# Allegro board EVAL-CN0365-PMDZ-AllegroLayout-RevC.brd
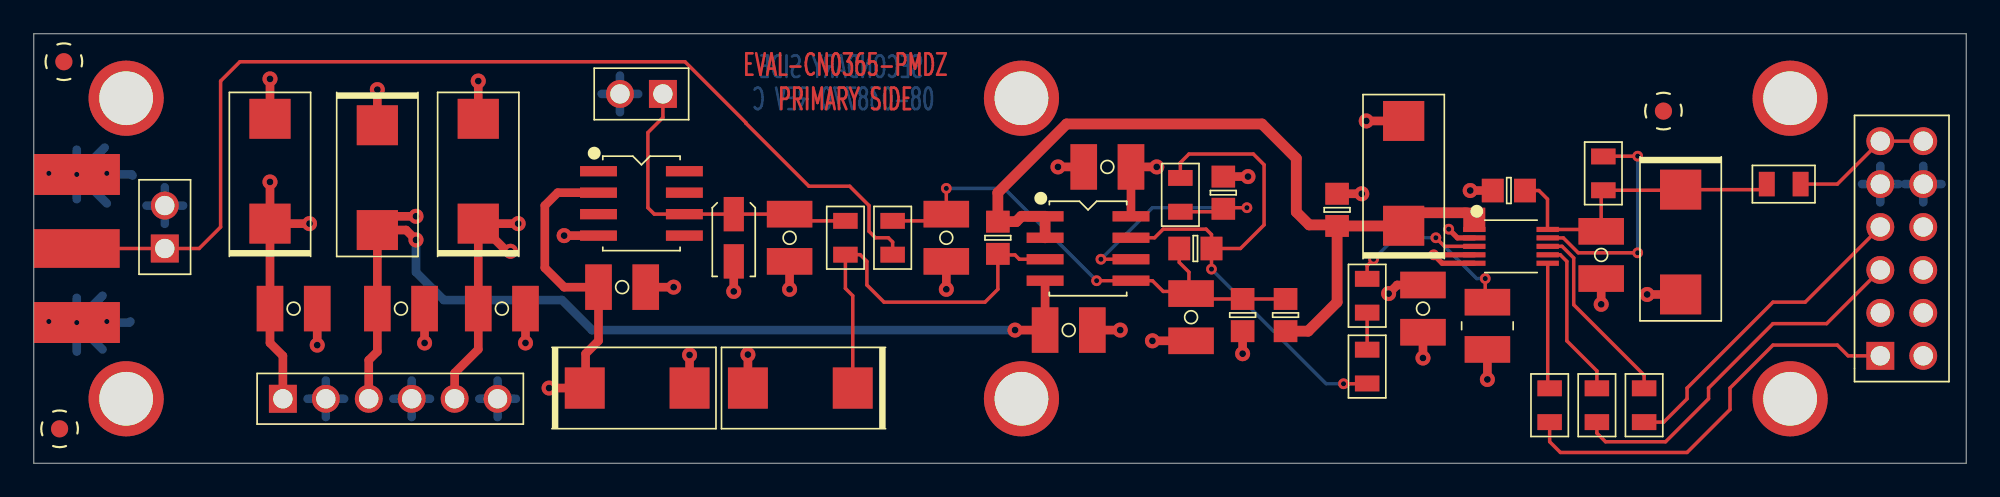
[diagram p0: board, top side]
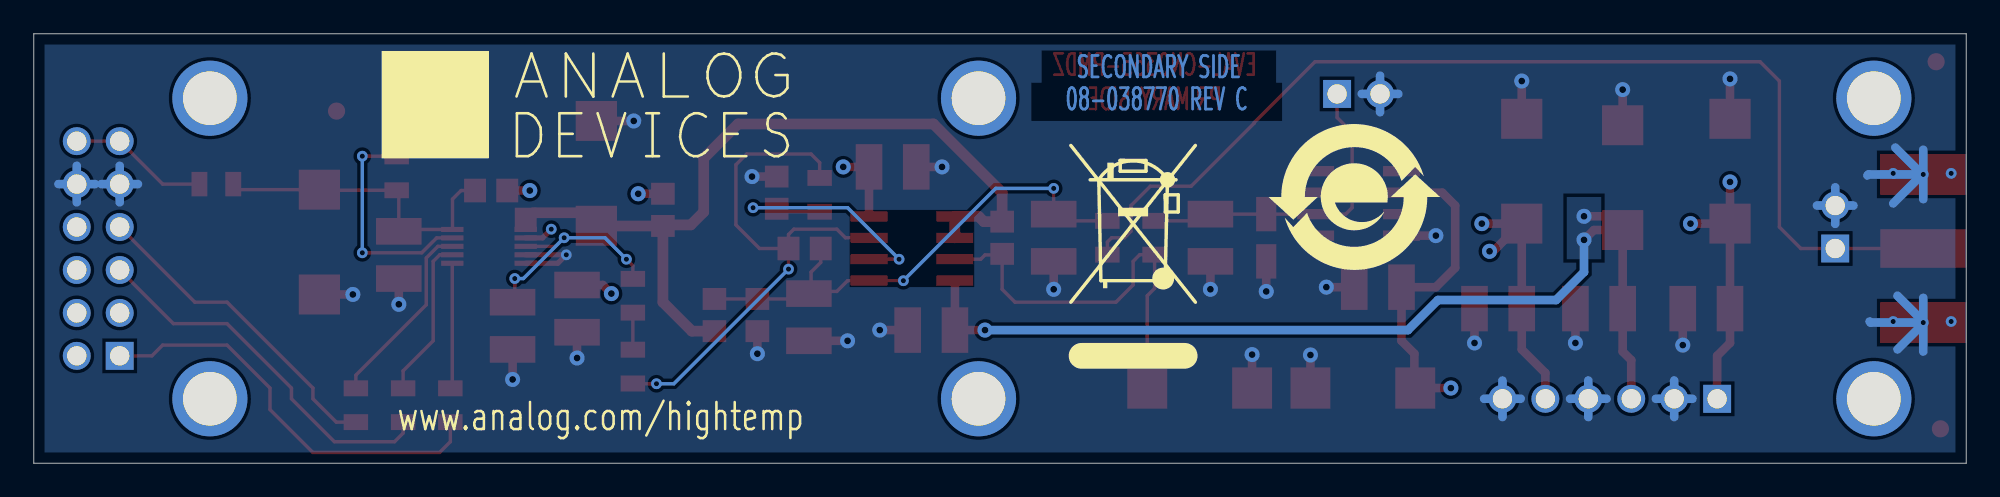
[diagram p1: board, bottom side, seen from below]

Outline 114.3 x 25.4 mm; copper layers: TOP, L2_GND, L3_PWR, BOTTOM. Coordinates in mm from the lower left corner of the outline.
Outline path: 0,25.4 0,0 114.3,0 114.3,25.4 0,25.4

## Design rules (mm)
net group CLS_POWER: nets VS+

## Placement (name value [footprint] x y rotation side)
C1  10uF  [C7343-31]  35.69 4.45 0 top
C2  0.1uF  [C1210]  34.8 10.41 0 top
C3  1uF  [C3216]  41.4 13.34 270 top
C4  0.1uF  [C1210]  44.7 13.34 270 top
C5  0.1uF  [C1210]  61.21 7.87 0 top
C6  TBD1210  [C1210]  53.98 13.34 270 top
C7  2700pF  [C1210-2]  85.98 8.13 270 top
C8  47uF  [C7343-31]  45.34 4.45 180 top
C9  TBD1210  [C1210]  68.45 8.64 270 top
C10  10uF  [C7343-31]  97.41 13.08 270 top
C11  0.1uF  [C1210]  92.71 12.32 270 top
C12  47uF  [C7343-31]  81.03 17.14 90 top
C15  0.1uF  [C1210]  82.17 9.14 270 top
C16  10uF  [C7343-31]  26.29 17.27 90 top
C17  0.1uF  [C1210]  27.69 9.14 0 top
C18  10uF  [C7343-31]  13.97 17.27 90 top
C19  0.1uF  [C1210]  15.37 9.14 0 top
C20  10uF  [C7343-31]  20.32 16.89 270 top
C21  0.1uF  [C1210]  21.72 9.14 0 top
C23  0.1uF  [C1210]  63.5 17.53 180 top
J1  JOHNSON142-0701-801  [CNJOHNSON142-0701-801]  2.54 12.7 180 top
J2  HTSW-106-08-G-D  [CNHDR2X6H330LD35_A]  109.22 6.35 90 top
JP1  0  [R0805H20]  50.8 13.34 90 top
JP2  0  [R0805H20]  67.82 15.88 90 top
JP3  0  [R0805H20]  78.87 5.71 90 top
JP4  0  [R0805H20]  92.84 17.14 90 top
JP5  0  [R0805H20]  89.66 3.43 270 top
JP6  0  [R0805H20]  92.46 3.43 270 top
JP7  0  [R0805H20]  95.25 3.43 270 top
JP8  0  [R0805H20]  103.5 16.51 0 top
NOREF  -  []  93.73 18.03 0 top
NOREF#2  -  []  167 303.53 0 top
NOREF#3  -  []  114.3 2.54 90 top
NOREF#4  -  []  3.81 2.54 0 top
NOREF#5  -  []  60.96 38.1 0 top
NOREF#6  -  []  114.3 27.94 180 top
NOREF#7  -  [unnamed#2]  58.42 21.59 0 top
NOREF#8  -  []  0 0 90 top
NOREF#9  -  [unnamed#2]  103.89 3.81 0 top
NOREF#10  -  []  -233.68 -149.86 0 top
NOREF#11  -  []  396.24 -2.54 0 top
NOREF#12  -  []  0 25.4 0 top
NOREF#13  -  [unnamed#2]  58.42 3.81 0 top
NOREF#14  -  []  0 0 90 top
NOREF#15  -  []  0 0 0 top
NOREF#16  -  [unnamed#2]  96.39 20.83 0 top
NOREF#17  -  []  3.81 27.94 270 top
NOREF#18  -  [unnamed#2]  1.52 2.03 0 top
NOREF#19  -  [unnamed#2]  1.78 23.75 0 top
NOREF#20  -  [unnamed#2]  5.46 3.81 0 top
NOREF#21  -  []  -76.2 -93.98 0 top
NOREF#22  -  []  -91.44 276.86 0 top
NOREF#23  -  [unnamed#2]  5.46 21.59 0 top
NOREF#24  -  [unnamed#2]  103.89 21.59 0 top
NOREF#25  -  []  40.01 22.48 180 bottom
NOREF#26  -  []  36.2 15.75 180 bottom
P1  TSW-101-14-T-D  [CNHDR2X1H428]  7.75 12.7 0 top
P2  TSW-101-14-T-D  [CNHDR2X1H428]  37.21 21.84 90 top
P3  HTSW-106-07-G-S  [CNHDR1X6H343]  14.73 3.81 0 top
R1  49.9  [R0805H20]  48.01 13.34 270 top
R2  TBD0805  [R0805]  57.02 13.34 90 top
R3  TBD0805  [R0805]  70.36 16 270 top
R4  TBD0805  [R0805]  71.5 8.76 270 top
R5  TBD0805  [R0805]  68.71 12.7 0 top
R6  49.9  [R0805H20]  78.87 9.91 90 top
R7  TBD0805  [R0805]  77.09 14.99 90 top
R8  TBD0805  [R0805]  74.04 8.76 90 top
R14  TBD0805  [R0805]  87.25 16.13 0 top
U1  ADR225HRZN  [SO8]  35.94 15.37 270 top
U2  AD8634HRZN  [SO8]  62.36 12.7 270 top
U3  AD7981  [RM10]  87.38 12.83 270 top

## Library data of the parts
C1 C10 C16 C18 C20 = CAPP: Tolerance: 10; User Part Number: UPN; part number: CAPP_SM-10UF,50V,10,E014348,C7343-31; tolerance: 10
C2 C4 C5 C11 C15 C17 C19 C21 C23 = CAP: Tolerance: 5; User Part Number: UPN; alternate symbols: (C0402H22_ALT,C0201-2,C0402_A,C0402_ALT,C0402L_ALT,C0603L_ALT); part number: CAP_SM-0.1UF,25V,5,E018667,C1210; tolerance: 5
C3 = CAPP: Tolerance: 10; User Part Number: UPN; part number: CAPP_SM-1UF,35V,10,E014170,C3216; tolerance: 10
C6 C9 = CAP: User Part Number: UPN; alternate symbols: (C0402H22_ALT,C0201-2,C0402_A,C0402_ALT,C0402L_ALT,C0603L_ALT); part number: CAP_SM-TBD1210,TBD1210,TBD1210,E016202,C1210
C7 = CAP: Tolerance: 5; User Part Number: UPN; alternate symbols: (C0402H22_ALT,C0201-2,C0402_A,C0402_ALT,C0402L_ALT,C0603L_ALT); part number: CAP_SM-2700PF,1000V,5,E021586,C1210-2; tolerance: 5
C8 C12 = CAPP: Tolerance: 10; User Part Number: UPN; part number: CAPP_SM-47UF,16V,10,E021837,C7343-31; tolerance: 10
J1 = CNBNC5P: User Part Number: UPN; alternate symbols: (CNAMPHENOL132255-11_ALT); part number: CNBNC5P_SM-JOHNSON142-0701-801,E000914,CNJOHNSON142-0701-801
J2 = CN12P_V3: User Part Number: UPN; part number: CN12P_V3_TH-HTSW-106-08-G-D,E021590,CNHDR2X6H330LD35_A
JP1-JP8 = RESJMPROPEN: Tolerance: 5; User Part Number: UPN; alternate symbols: (R0402_ALT); part number: RESJMPROPEN_SM-0,E021851,1/8W,5,R0805H20; tolerance: 5
P1 P2 = CN2P: User Part Number: UPN; part number: CN2P_TH-TSW-101-14-T-D,E016220,CNHDR2X1H428
P3 = CN6P: User Part Number: UPN; part number: CN6P_TH-HTSW-106-07-G-S,E021853,CNHDR1X6H343
R1 R6 = RES: Tolerance: 0.1; User Part Number: UPN; alternate symbols: (RRAD984L1500W75H520LD32;TO220H590_ALT;R0402_A;R0603_A,R0402_ALT); part number: RES_SM-49.9,E021588,1/5W,0.1,R0805H20; tolerance: 0.1
R2-R5 R7 R8 R14 = RES: User Part Number: UPN; alternate symbols: (RRAD984L1500W75H520LD32;TO220H590_ALT;R0402_A;R0603_A,R0402_ALT); part number: RES_SM-TBD0805,E004051,TBD0805,TBD0805,R0805
U1 = ADR225: User Part Number: UPN; part number: ADR225_SM-ADR225HRZN,E019946,SO8
U2 = AD8634: User Part Number: UPN; part number: AD8634_SM-AD8634HRZN,E020461,SO8
U3 = AD7981: User Part Number: UPN; part number: AD7981_SM-AD7981,E021331,RM10

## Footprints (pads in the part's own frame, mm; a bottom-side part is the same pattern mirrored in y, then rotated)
C1210
  rect 1.575x2.692 smd: 1(-1.397,0) 2(1.397,0)
C1210-2
  rect 1.575x2.692 smd: 1(-1.397,0) 2(1.397,0)
C3216
  rect 2.032x1.194 smd: N(1.397,0) P(-1.397,0)
C7343-31
  rect 2.362x2.438 smd: N(3.1,0) P(-3.1,0)
CNHDR1X6H343
  rect 1.651x1.651 hole 1.143: 1(0,0)
  round 1.651 hole 1.143: 2(2.54,0) 3(5.08,0) 4(7.62,0) 5(10.16,0) 6(12.7,0)
CNHDR2X1H428
  rect 1.651x1.651 hole 1.143: 1(0,0)
  round 1.651 hole 1.143: 2(0,2.54)
CNHDR2X6H330LD35_A
  rect 1.651x1.651 hole 1.143: 1(0,0)
  round 1.651 hole 1.143: 2(2.54,0) 3(5.08,0) 4(7.62,0) 5(10.16,0) 6(12.7,0) 7(0,-2.54) 8(2.54,-2.54) 9(5.08,-2.54) 10(7.62,-2.54) 11(10.16,-2.54) 12(12.7,-2.54)
CNJOHNSON142-0701-801
  rect 5.08x2.286 smd: 1(0,0)
  rect 5.08x2.413 smd: 2(0,4.381) 3(0,4.381) 4(0,-4.381) 5(0,-4.381)
R0805
  rect 1.295x1.397 smd: 1(-0.953,0) 2(0.953,0)
R0805H20
  rect 0.94x1.448 smd: 1(-1,0) 2(1,0)
RM10
  rect 0.305x1.321 smd: 1(-1,-2.171) 2(-0.5,-2.171) 3(0,-2.171) 4(0.5,-2.171) 5(1,-2.171) 6(1,2.171) 7(0.5,2.171) 8(0,2.171) 9(-0.5,2.171) 10(-1,2.171)
SO8
  rect 0.61x2.184 smd: 1(-1.905,-2.54) 2(-0.635,-2.54) 3(0.635,-2.54) 4(1.905,-2.54) 5(1.905,2.54) 6(0.635,2.54) 7(-0.635,2.54) 8(-1.905,2.54)
unnamed#2
  round 4.445 hole 3.175 unplated: (0,0)

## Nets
AGND: C1.N(N2) C2.2(N2) C3.N(N2) C4.2(N2) C5.2(N2) C6.2(N2) C7.2(N2) C8.N(N2) C9.2(N2) C10.N(N2) C11.2(N2) C12.N(N2) C15.2(N2) C16.N(N2) C17.2(N2) C18.N(N2) C19.2(N2) C20.P(N1) C21.2(N2) C23.2(N2) J1.2(SH1) J1.3(SH2) J1.4(SH3) J1.5(SH4) J2.5(GND1) J2.11(GND2) P1.2(N2) P2.2(N2) P3.2(N2) P3.4(N4) P3.6(N6) R3.1(N1) R4.2(N2) U1.4(GND) U3.4(IN-) U3.5(GND)
VDD: C15.1(N1) C16.P(N1) C17.1(N1) P3.5(N5) R7.2(N2) R14.1(N1) U3.2(VDD)
CNV: JP5.1(S1) U3.6(CNV)
REF: C3.P(N1) C4.1(N1) P2.1(N1) R1.1(N1) U1.6(OUTPUT)
REF_BUF: C12.P(N1) R2.2(N2) R7.1(N1) R8.1(N1) U2.1(OUT) U2.2(-IN) U3.1(REF)
SCK: JP7.1(S1) U3.8(SCK)
SDI: JP4.2(S2) U3.9(SDI)
SDO: JP6.1(S1) U3.7(SDO)
UNNAMED_2_AD7981_I1_IN: C7.1(N1) R6.2(N2) U3.3(IN+)
UNNAMED_2_AD8634_I44__1: JP2.1(S1) R3.2(N2) U2.6(-IN)
UNNAMED_2_AD8634_I44_OUT: JP2.2(S2) JP3.1(S1) R5.2(N2) U2.7(OUT)
UNNAMED_2_AD8634_I149_: C8.P(N1) R1.2(N2) R2.1(N1) U2.3(+IN)
UNNAMED_2_CAP_I204_N1: C6.1(N1) C9.1(N1) JP1.2(S2) R4.1(N1) R5.1(N1) R8.2(N2) U2.5(+IN)
UNNAMED_2_CN12PV3_I180_P1: J2.1(P1) JP5.2(S2)
UNNAMED_2_CN12PV3_I180_P3: J2.3(P3) JP6.2(S2)
UNNAMED_2_CN12PV3_I180_P4: J2.4(P4) JP7.2(S2)
UNNAMED_2_CN12PV3_I180_VCC1: J2.6(VCC1) J2.12(VCC2) JP8.2(S2)
UNNAMED_2_CNBNC5P_I137_CNTR: J1.1(CNTR) JP1.1(S1) P1.1(N1)
UNNAMED_2_RES_I189_N1: JP3.2(S2) R6.1(N1)
VIO: C10.P(N1) C11.1(N1) JP4.1(S1) JP8.1(S1) R14.2(N2) U3.10(VIO)
VS+: C1.P(N1) C2.1(N1) C18.P(N1) C19.1(N1) C23.1(N1) P3.1(N1) U1.2(VS) U2.8(V+)
VS-: C5.1(N1) C20.N(N2) C21.1(N1) P3.3(N3) U2.4(V-)

Pads without a net: J2 2 7 8 9 10; U1 1 3 5 7 8

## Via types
v1: diameter 0.635, hole 0.305, TOP to BOTTOM, 19 vias
v2: diameter 0.889, hole 0.406, TOP to BOTTOM, 35 vias

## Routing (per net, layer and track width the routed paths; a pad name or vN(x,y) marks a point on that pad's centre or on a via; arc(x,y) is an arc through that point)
AGND: length 130.2
  TOP w0.305: U3.4 v1(82.8,12.33) 83.3,11.83 U3.5
  TOP w0.508: C18.N v2(13.97,22.73) ; C1.N v2(38.79,6.4) ; R4.2 v2(71.5,6.48) ; C7.2 v2(85.98,4.95) ; C16.N v2(26.29,22.61) ; U1.4 v2(31.37,13.46) ; C17.2 v2(29.08,7.11) ; C10.N v2(95.43,9.98) ; C4.2 v2(44.7,10.29) ; C6.2 v2(53.98,10.29) ; R3.1 v2(71.82,16.95) ; C21.2 v2(23.11,7.11) ; C5.2 v2(64.26,7.87) ; C19.2 v2(16.76,6.99) ; C9.2 v2(66.17,7.24) ; C3.N v2(41.4,10.16) ; C11.2 v2(92.71,9.4) ; C23.2 v2(60.58,17.53) ; C15.2 v2(82.17,6.22) ; C12.N v2(78.81,20.25) ; C20.P v2(20.32,22.1) ; 42.24,4.45 v2(42.24,6.42) ; C2.2 v2(37.85,10.41)
  L2_GND w0.508: J2.11 111.76,17.59 ; J2.11 111.76,15.43 ; J2.11 112.84,16.51 ; J2.11 110.68,16.51 ; 21.27,3.81 P3.4 ; P3.4 22.35,2.73 ; P3.4 23.43,3.81 ; P3.4 22.35,4.89 ; 34.67,21.84 35.75,21.84 ; 34.67,21.84 33.59,21.84 ; 34.67,21.84 34.67,22.92 ; 34.67,21.84 34.67,20.76 ; 27.43,2.73 P3.6 ; P3.6 27.43,4.89 ; P3.6 28.51,3.81 ; P3.6 26.35,3.81 ; 108.14,16.51 J2.5 ; J2.5 109.22,15.43 ; J2.5 109.22,17.59 ; J2.5 110.3,16.51 ; P3.2 17.27,4.89 ; P3.2 18.35,3.81 ; P3.2 16.19,3.81 ; P3.2 17.27,2.73 ; P1.2 8.83,15.24 ; P1.2 6.67,15.24 ; P1.2 7.75,14.16 ; P1.2 7.75,16.32
  BOTTOM w0.508: P3.6 27.43,4.89 ; P3.6 26.35,3.81 ; P3.6 28.51,3.81 ; P3.6 27.43,2.73 ; 4.06,9.91 2.54,8.38 ; 2.54,8.38 2.54,9.78 ; 2.54,8.38 v1(2.54,8.32) ; P3.2 17.27,4.89 ; P3.2 17.27,2.73 ; P3.2 18.35,3.81 ; P3.2 16.19,3.81 ; J2.5 109.22,17.59 ; J2.5 110.3,16.51 ; J2.5 108.14,16.51 ; J2.5 109.22,15.43 ; 4.25,8.32 5.65,8.32 5.71,8.38 ; 4.25,8.32 v1(4.32,8.38) ; 4.25,8.32 v1(2.54,8.32) ; 4.25,17.08 2.6,17.08 ; 4.25,17.08 v1(4.32,17.14) ; 4.25,17.08 5.78,17.08 5.84,17.02 ; 2.6,17.08 v1(2.54,17.08) ; 2.6,17.08 4.19,18.67 ; 2.6,17.08 4.32,15.37 ; J2.11 112.84,16.51 ; J2.11 110.68,16.51 ; J2.11 111.76,15.43 ; J2.11 111.76,17.59 ; 4.06,6.73 2.54,8.25 ; 2.54,8.25 v1(2.54,8.32) ; 2.54,8.25 2.54,6.6 ; 34.67,21.84 35.75,21.84 ; 34.67,21.84 34.67,22.92 ; 34.67,21.84 33.59,21.84 ; 34.67,21.84 34.67,20.76 ; v1(2.54,17.08) 2.54,15.62 ; v1(2.54,17.08) 2.54,18.54 ; P1.2 8.83,15.24 ; P1.2 6.67,15.24 ; P1.2 7.75,14.16 ; P1.2 7.75,16.32 ; P3.4 22.35,4.89 ; P3.4 22.35,2.73 ; P3.4 21.27,3.81 ; P3.4 23.43,3.81
  vias: v1(0.89,17.14) v1(0.89,8.38)
VDD: length 22.6
  TOP w0.305: U3.2 84.21,13.33 v1(83.69,13.84)
  TOP w0.508: 26.34,14.17 27.98,12.54 v2(28.19,12.54) ; 26.34,14.17 C16.P C17.1 26.29,6.73 24.89,5.33 P3.5 ; 26.34,14.17 v2(28.65,14.17) ; v2(80.14,10.03) 80.64,10.54 C15.1 ; R14.1 v2(84.96,16.13) ; R7.2 v2(78.55,15.94)
CNV: length 7.4
  TOP w0.203: U3.6 89.55,4.54 JP5.1
REF: length 19.1
  TOP w0.203: P2.1 37.21,20.45 36.32,19.56 36.32,15.11 36.7,14.73 U1.6 C3.P C4.1 45.1,14.33 R1.1
REF_BUF: length 48.3
  TOP w0.635: R7.1 77.03,14.1 75.44,14.1 74.68,14.86 74.68,18.03 72.64,20.07 61.09,20.07 57.02,16 R2.2 58.1,14.29 58.42,14.61 U2.1 U2.2 ; R7.1 81.01,14.03 C12.P 81.79,14.81 84.76,14.81 ; R7.1 77.09,9.53 75.37,7.81 R8.1
SCK: length 11.3
  TOP w0.203: JP7.1 95.25,5.21 91.08,9.37 91.08,12.14 90.4,12.83 U3.8
SDI: length 13.4
  TOP w0.203: v1(94.87,18.16) 92.85,18.16 JP4.2 ; v1(94.87,12.45) 91.35,12.45 90.47,13.33 U3.9
  BOTTOM w0.203: v1(94.87,12.45) v1(94.87,18.16)
SDO: length 9.5
  TOP w0.203: JP6.1 92.46,5.46 90.68,7.24 90.68,11.94 90.29,12.33 U3.7
UNNAMED_2_AD7981_I1_IN: length 13.4
  TOP w0.203: R6.2 78.87,11.68 v1(79.25,12.07) ; U3.3 83.44,12.83 v1(82.93,13.34) ; C7.1 85.85,9.65 v1(85.85,10.92)
  BOTTOM w0.203: v1(85.85,10.92) 85.34,10.92 v1(82.93,13.34) 80.52,13.34 v1(79.25,12.07)
UNNAMED_2_AD8634_I44__1: length 15.7
  TOP w0.203: 64.9,12.07 v1(63.12,12.07) ; JP2.1 70.18,14.88 R3.2 70.42,15.11 v1(71.75,15.11)
  BOTTOM w0.203: v1(71.75,15.11) 66.17,15.11 v1(63.12,12.07)
UNNAMED_2_AD8634_I44_OUT: length 32.7
  TOP w0.203: 64.9,13.34 66.29,13.34 66.8,13.84 69.34,13.84 69.66,13.53 R5.2 ; R5.2 v1(69.66,11.48) ; R5.2 71.37,12.7 72.77,14.1 72.77,17.65 72.14,18.29 68.33,18.29 67.82,17.78 JP2.2 ; JP3.1 78.85,4.7 v1(77.47,4.7)
  BOTTOM w0.203: v1(77.47,4.7) 76.44,4.7 v1(69.66,11.48)
UNNAMED_2_AD8634_I149_: length 24.4
  TOP w0.203: U2.3 58.29,12.07 58.04,12.32 57.09,12.32 R2.1 57.02,10.29 56.26,9.53 50.29,9.53 49.28,10.54 49.28,11.94 48.88,12.34 R1.2 48.01,10.34 48.44,9.91 C8.P
UNNAMED_2_CAP_I204_N1: length 30.4
  TOP w0.203: R5.1 67.75,11.87 68.33,11.3 68.33,10.16 ; 68.33,10.16 C9.1 68.77,9.72 R4.1 R8.2 ; 68.33,10.16 66.8,10.16 66.17,10.8 v1(62.87,10.8) ; JP1.2 53.58,14.33 C6.1 v1(53.98,16.26)
  BOTTOM w0.203: v1(62.87,10.8) 57.4,16.26 v1(53.98,16.26)
UNNAMED_2_CN12PV3_I180_P1: length 24.6
  TOP w0.203: J2.1 107.31,6.35 106.68,6.99 102.87,6.99 100.33,4.45 100.33,3.17 97.79,0.64 90.3,0.64 89.66,1.27 JP5.2
UNNAMED_2_CN12PV3_I180_P3: length 22.2
  TOP w0.203: JP6.2 92.46,1.78 92.96,1.27 96.52,1.27 99.06,3.81 99.06,4.45 102.87,8.25 106.05,8.25 J2.3
UNNAMED_2_CN12PV3_I180_P4: length 19.1
  TOP w0.203: JP7.2 96.41,2.43 97.79,3.81 97.79,4.45 102.87,9.53 104.78,9.53 J2.4
UNNAMED_2_CN12PV3_I180_VCC1: length 8.3
  TOP w0.203: JP8.2 106.68,16.51 J2.6 J2.12
UNNAMED_2_CNBNC5P_I137_CNTR: length 64
  TOP w0.203: J1.1 P1.1 9.78,12.7 11.05,13.97 11.05,22.61 12.19,23.75 38.52,23.75 42.11,20.15 42.11,20.12 45.85,16.38 48.26,16.38 49.4,15.24 49.4,13.72 49.78,13.34 50.55,13.34 50.8,13.08 JP1.1
UNNAMED_2_RES_I189_N1: length 2.2
  TOP w0.203: JP3.2 R6.1
VIO: length 18.9
  TOP w0.203: JP8.1 102.18,16.18 C10.P 97.37,16.15 JP4.1 92.71,16.02 C11.1 92.6,13.83 U3.10 89.53,13.84 89.53,15.62 89.03,16.13 R14.2
VS+: length 39.2
  TOP w0.508: P3.1 14.73,6.35 13.97,7.11 C19.1 C18.P ; C18.P v2(16.31,14.17) ; C18.P v2(13.97,16.64) ; v2(30.48,4.45) C1.P 32.64,4.5 32.64,6.48 33.4,7.24 C2.1 31.37,10.41 30.23,11.56 30.23,15.24 30.99,16 U1.2 ; 64.9,14.61 64.9,17.53 v2(66.42,17.53)
VS-: length 58.8
  TOP w0.508: v2(58.04,7.87) C5.1 U2.4 ; v2(22.61,13.21) 22.02,13.79 C20.N ; C20.N 21.13,14.61 v2(22.61,14.61) ; C20.N C21.1 20.32,6.6 19.81,6.1 P3.3
  BOTTOM w0.508: v2(22.61,13.21) 22.61,11.3 24.26,9.65 31.24,9.65 33.02,7.87 v2(58.04,7.87)

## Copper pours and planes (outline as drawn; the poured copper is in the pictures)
AGND on BOTTOM: 0.64,24.77 0.64,0.64 113.67,0.64 113.67,24.77 ; 1 cut-out
AGND on L2_GND: 0.64,0.64 0.64,24.77 113.67,24.77 113.67,0.64 ; 1 cut-out
VDD on L3_PWR: 87.3,14.82 81.83,9.35 77.94,9.35 73.87,13.41 68.18,19.1 65.58,19.1 64.57,18.08 64.57,15.04 58.62,15.04 58.62,13.41 33.7,13.41 32.17,11.89 26.63,11.89 26.19,12.33 25.73,12.78 25.73,16.3 25.99,16.56 55.85,16.56 58.17,18.87 59.56,18.87 64.16,23.47 72.09,23.47 78.16,17.4 86.58,17.4 87.3,16.68
REF_BUF on TOP (solid shape): 85.85,13.69 84.56,13.69 84.56,15.11 85.85,15.11
VS+ on L3_PWR (solid shape): outline of 4313 points within 0.64,0.64 113.67,24.76
VS- on BOTTOM: 21.59,15.75 21.59,12.07 23.62,12.07 23.62,15.75

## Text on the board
BOTTOM: SECONDARY SIDE | 08-038770 REV C
Ref Des/Silkscreen Bottom: www.analog.com/hightemp
TOP: EVAL-CN0365-PMDZ | PRIMARY SIDE
PAGE_OUTLINE: B | C | ECR-047755 | ECR-051077 | 19SEP14 | 24JAN15 | J.WATSON
DIMENSION: MAX DIAMETER
User.15: ENIG (Electroless Nickel/Immersion Gold) | PER IPC-4552 LATEST REVISION | HOMOGENOUS MATERIALS IN THIS BOARD SHALL BE COMPLIANT | THE EU RoHS DIRECTIVE 2002/95/EC
User.17: L2 GND | 08-      -07
User.18: L3 PWR | 08-      -08
User.21: 15.    THRU VIAS FILLED WITH NON-CONDUCTIVE EPOXY AND PLATED OVER. | COPLANAR ON BOTH SIDES WITHIN .001 INCH PRIOR TO FINAL PLATING.
User.45: J.WATSON | L.NERETTE | 06AUG14 | ECR-047755 | ECR-051077 | B | C | 19SEP14 | 24JAN15 | FIGURE | SIZE | 12.0 | 16.0 | 45.0 | 125.0 | PLATED | NON-PLATED | FINISHED HOLES IN MILS | ALL UNITS ARE IN MILS | QTY | 19 | 35 | 22 | 6 | TOLERANCE/NOTES
